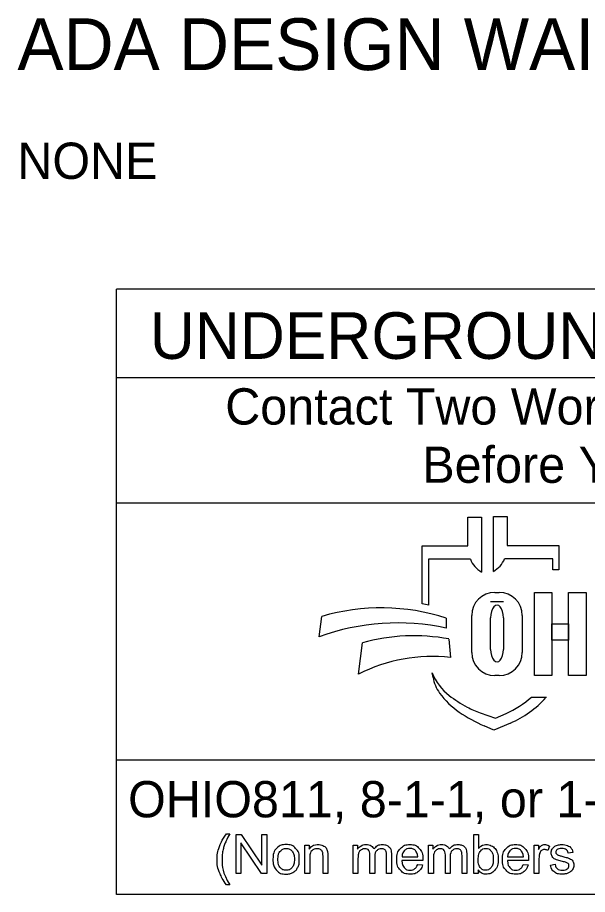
# Model space of a CAD drawing. Extents: x 0 to 34, y 0 to 22.
# Drawn here: x 1.995 to 4.196, y 2.143 to 5.529 of the extents above; entities that cross this region are included whole.
import ezdxf

# ---------------------------------------------------------------- set-up
doc = ezdxf.new("R2010")
doc.units = 0
doc.layers.add('SH_Data', color=7, linetype='Continuous')
doc.layers.add('SH_Text', color=7, linetype='Continuous')

msp = doc.modelspace()

# ---------------------------------------------------------------- linework, layer by layer
at = {"layer": 'SH_Data'}
for p, q in [((2.3775, 2.1428), (2.3775, 4.4803)), ((6.6275, 4.4803), (2.3775, 4.4803)), ((2.3775, 4.1387), (6.6275, 4.1387)), ((2.3775, 3.6553), (6.6275, 3.6553)), ((6.6275, 2.6607), (2.3775, 2.6607)), ((6.6275, 2.1428), (2.3775, 2.1428))]:
    msp.add_line(p, q, dxfattribs=at)
at = {"layer": 'SH_Text'}
for p, q in [((3.7335, 3.4883), (3.7335, 3.5998)), ((3.7335, 3.5998), (3.7872, 3.5998)), ((3.7872, 3.5998), (3.7872, 3.3877)), ((3.8329, 3.39), (3.8329, 3.6021)), ((3.8329, 3.6021), (3.8865, 3.6021)), ((3.8865, 3.6021), (3.8865, 3.4906)), ((3.5576, 3.2644), (3.5576, 3.4883)), ((3.5576, 3.4883), (3.7335, 3.4883)), ((3.8865, 3.4906), (4.0857, 3.4906)), ((4.0857, 3.4906), (4.0857, 3.3968)), ((3.5828, 3.4369), (3.5828, 3.26)), ((3.7439, 3.4369), (3.5828, 3.4369)), ((4.0625, 3.4392), (3.8761, 3.4392)), ((4.0625, 3.3968), (4.0625, 3.4392)), ((4.0857, 3.3968), (4.0625, 3.3968)), ((3.8385, 3.3091), (3.8551, 3.3091)), ((3.8718, 3.2721), (3.822, 3.2721)), ((3.7491, 3.0776), (3.7491, 3.2196)), ((3.9445, 3.2196), (3.9445, 3.0776)), ((3.1602, 3.1381), (3.1696, 3.2162)), ((3.6509, 3.2097), (3.6509, 3.1709)), ((3.822, 3.089), (3.822, 3.2114)), ((3.8718, 3.2114), (3.8718, 3.089)), ((3.6608, 3.1291), (3.6671, 3.0582)), ((3.312, 2.9936), (3.3267, 3.1137)), ((3.5997, 2.9807), (3.5967, 2.9986)), ((3.8551, 2.9882), (3.8385, 2.9882)), ((3.98, 2.9048), (4.0375, 2.9048)), ((3.7816, 2.8444), (3.841, 2.8239)), ((3.841, 2.8239), (3.8821, 2.8417)), ((3.835, 2.7769), (3.7976, 2.7934)), ((3.8983, 2.8044), (3.835, 2.7769))]:
    msp.add_line(p, q, dxfattribs=at)
for points in [[(3.991, 3.3081), (4.0589, 3.3081), (4.0589, 2.9881), (3.991, 2.9881)], [(4.1231, 3.3081), (4.1911, 3.3081), (4.1911, 2.9881), (4.1231, 2.9881)], [(4.0589, 3.1882), (4.1231, 3.1882), (4.1231, 3.1242), (4.0589, 3.1242)]]:
    msp.add_lwpolyline(points, close=True, dxfattribs=at)
for points in [[(2.8021, 2.3766), (2.8153, 2.3766)], [(2.8389, 2.2239), (2.8389, 2.3741), (2.8592, 2.3741), (2.9382, 2.2561), (2.9382, 2.3741), (2.9572, 2.3741), (2.9572, 2.2239), (2.9369, 2.2239), (2.8579, 2.3419), (2.8579, 2.2239), (2.8389, 2.2239)], [(3.7743, 2.2239), (3.7573, 2.2239), (3.7573, 2.3741), (3.7757, 2.3741), (3.7757, 2.3206)], [(3.1048, 2.2239), (3.1048, 2.3328), (3.1214, 2.3328), (3.1214, 2.3173)], [(3.2912, 2.2239), (3.2912, 2.3328), (3.3077, 2.3328), (3.3077, 2.3174)], [(3.5826, 2.2239), (3.5826, 2.3328), (3.5991, 2.3328), (3.5991, 2.3174)], [(3.9904, 2.2239), (3.9904, 2.3328), (4.007, 2.3328), (4.007, 2.3163)], [(4.0495, 2.3293), (4.043, 2.3122)], [(4.1394, 2.3046), (4.1213, 2.3022)], [(3.1233, 2.2833), (3.1233, 2.2239), (3.1048, 2.2239)], [(3.1932, 2.2908), (3.1932, 2.2239), (3.1748, 2.2239), (3.1748, 2.2901)], [(3.3097, 2.2803), (3.3097, 2.2239), (3.2912, 2.2239)], [(3.3743, 2.2871), (3.3743, 2.2239), (3.3559, 2.2239), (3.3559, 2.2946)], [(3.4388, 2.2986), (3.4388, 2.2239), (3.4203, 2.2239), (3.4203, 2.2924)], [(3.56, 2.2736), (3.4788, 2.2736)], [(3.4799, 2.2887), (3.5406, 2.2887)], [(3.601, 2.2803), (3.601, 2.2239), (3.5826, 2.2239)], [(3.6657, 2.2871), (3.6657, 2.2239), (3.6473, 2.2239), (3.6473, 2.2946)], [(3.7301, 2.2986), (3.7301, 2.2239), (3.7117, 2.2239), (3.7117, 2.2924)], [(3.968, 2.2736), (3.8868, 2.2736)], [(3.8879, 2.2887), (3.9486, 2.2887)], [(4.0088, 2.2809), (4.0088, 2.2239), (3.9904, 2.2239)], [(3.5404, 2.2591), (3.5595, 2.2567)], [(3.7743, 2.2375), (3.7743, 2.2239)], [(3.9484, 2.2591), (3.9675, 2.2567)], [(4.053, 2.2564), (4.0712, 2.2593)], [(2.8153, 2.1798), (2.8021, 2.1798)]]:
    msp.add_lwpolyline(points, dxfattribs=at)
for centre, radius, start, end in [((3.8353, 3.4736), 0.0985, 201.9296, 240.7469), ((3.7847, 3.476), 0.0985, 299.2531, 338.0704), ((3.8385, 3.2196), 0.0895, 90, 180), ((3.8551, 3.2196), 0.0895, 0, 90), ((3.4295, 2.4554), 0.8191, 79.2074, 81.0007), ((3.3997, 2.4302), 0.8191, 72.1402, 106.3144), ((3.4628, 2.2991), 0.8919, 77.8238, 109.8274), ((3.5267, 2.4094), 0.7322, 79.44, 105.8467), ((3.5987, 2.4262), 0.6357, 83.8248, 116.8021), ((3.8385, 3.0776), 0.0895, 180, 270), ((3.8551, 3.0776), 0.0895, 270, 0), ((3.7841, 3.0707), 0.2008, 201.0457, 232.5314), ((3.741, 3.0048), 0.1433, 189.6817, 216.0884), ((3.8747, 3.1022), 0.3088, 216.0884, 235.7167), ((3.9766, 3.3219), 0.5173, 232.5314, 241.794), ((3.7387, 3.1722), 0.3602, 293.4582, 312.0712), ((3.7387, 3.1722), 0.401, 293.4582, 317.8286), ((4.0412, 3.3465), 0.6044, 235.7167, 246.2325), ((3.8914, 3.1631), 0.3371, 241.794, 250.9821)]:
    msp.add_arc(centre, radius, start, end, dxfattribs=at)
for centre, start_param, end_param in [((3.8469, 3.2114), 4.712389, 7.853982), ((3.8469, 3.089), 1.570796, 4.712389)]:
    msp.add_ellipse(centre, major_axis=(0, 0.0484), ratio=0.514403, start_param=start_param, end_param=end_param, dxfattribs=at)
for points in [[(2.8021, 2.1798), (2.7869, 2.199), (2.7763, 2.2248), (2.7657, 2.2506), (2.7657, 2.2783), (2.7657, 2.3026), (2.7736, 2.325), (2.7829, 2.3509), (2.8021, 2.3766)], [(2.8153, 2.3766), (2.8029, 2.3553), (2.7989, 2.3462), (2.7927, 2.332), (2.7891, 2.3167), (2.7847, 2.2975), (2.7847, 2.2782), (2.7847, 2.2289), (2.8153, 2.1798)], [(2.9814, 2.2783), (2.9814, 2.3085), (2.9981, 2.3231), (3.0122, 2.3352), (3.0323, 2.3352), (3.0547, 2.3352), (3.069, 2.3205), (3.0832, 2.3058), (3.0832, 2.2799), (3.0832, 2.2589), (3.0769, 2.2469), (3.0706, 2.2348), (3.0586, 2.2282), (3.0466, 2.2215), (3.0323, 2.2215), (3.0095, 2.2215), (2.9954, 2.2362), (2.9814, 2.2508), (2.9814, 2.2783)], [(3.0003, 2.2783), (3.0003, 2.2574), (3.0094, 2.247), (3.0185, 2.2366), (3.0323, 2.2366), (3.046, 2.2366), (3.0551, 2.2471), (3.0642, 2.2575), (3.0642, 2.279), (3.0642, 2.2991), (3.0551, 2.3095), (3.0459, 2.3199), (3.0323, 2.3199), (3.0185, 2.3199), (3.0094, 2.3096), (3.0003, 2.2992), (3.0003, 2.2783)], [(3.1214, 2.3173), (3.1334, 2.3352), (3.156, 2.3352), (3.1659, 2.3352), (3.1741, 2.3316), (3.1823, 2.3281), (3.1864, 2.3224), (3.1905, 2.3166), (3.1922, 2.3087), (3.1932, 2.3036), (3.1932, 2.2908)], [(3.1748, 2.2901), (3.1748, 2.3013), (3.1726, 2.3069), (3.1705, 2.3125), (3.165, 2.3158), (3.1595, 2.3191), (3.1521, 2.3191), (3.1404, 2.3191), (3.1318, 2.3117), (3.1233, 2.3042), (3.1233, 2.2833)], [(3.3077, 2.3174), (3.3128, 2.3254), (3.3214, 2.3303), (3.3299, 2.3352), (3.3407, 2.3352), (3.3528, 2.3352), (3.3606, 2.3301), (3.3683, 2.3251), (3.3715, 2.3161), (3.3844, 2.3352), (3.4051, 2.3352), (3.4213, 2.3352), (3.43, 2.3262), (3.4388, 2.3172), (3.4388, 2.2986)], [(3.3559, 2.2946), (3.3559, 2.3069), (3.3514, 2.313), (3.3469, 2.3191), (3.3366, 2.3191), (3.3288, 2.3191), (3.3222, 2.315), (3.3156, 2.311), (3.3126, 2.3031), (3.3097, 2.2952), (3.3097, 2.2803)], [(3.4203, 2.2924), (3.4203, 2.3035), (3.4185, 2.3083), (3.4168, 2.3132), (3.412, 2.3162), (3.4073, 2.3191), (3.401, 2.3191), (3.3895, 2.3191), (3.3819, 2.3115), (3.3743, 2.3039), (3.3743, 2.2871)], [(3.5595, 2.2567), (3.555, 2.24), (3.5428, 2.2307), (3.5306, 2.2215), (3.5117, 2.2215), (3.4878, 2.2215), (3.4738, 2.2362), (3.4598, 2.2509), (3.4598, 2.2774), (3.4598, 2.3049), (3.474, 2.32), (3.4881, 2.3352), (3.5106, 2.3352), (3.5324, 2.3352), (3.5463, 2.3203), (3.5601, 2.3055), (3.5601, 2.2785), (3.5601, 2.2769), (3.56, 2.2736)], [(3.5406, 2.2887), (3.5394, 2.3025), (3.5337, 2.3094), (3.5249, 2.3201), (3.5108, 2.3201), (3.4981, 2.3201), (3.4894, 2.3115), (3.4808, 2.303), (3.4799, 2.2887)], [(3.5991, 2.3174), (3.6042, 2.3254), (3.6127, 2.3303), (3.6212, 2.3352), (3.6321, 2.3352), (3.6442, 2.3352), (3.6519, 2.3301), (3.6597, 2.3251), (3.6628, 2.3161), (3.6758, 2.3352), (3.6965, 2.3352), (3.7127, 2.3352), (3.7214, 2.3262), (3.7301, 2.3172), (3.7301, 2.2986)], [(3.6473, 2.2946), (3.6473, 2.3069), (3.6428, 2.313), (3.6383, 2.3191), (3.628, 2.3191), (3.6202, 2.3191), (3.6136, 2.315), (3.607, 2.311), (3.604, 2.3031), (3.601, 2.2952), (3.601, 2.2803)], [(3.7117, 2.2924), (3.7117, 2.3035), (3.7099, 2.3083), (3.7081, 2.3132), (3.7034, 2.3162), (3.6987, 2.3191), (3.6923, 2.3191), (3.6809, 2.3191), (3.6733, 2.3115), (3.6657, 2.3039), (3.6657, 2.2871)], [(3.7741, 2.2792), (3.7741, 2.2596), (3.7794, 2.2509), (3.7881, 2.2366), (3.8029, 2.2366), (3.815, 2.2366), (3.8238, 2.2471), (3.8326, 2.2576), (3.8326, 2.2784), (3.8326, 2.2998), (3.8241, 2.3099), (3.8157, 2.3201), (3.8038, 2.3201), (3.7917, 2.3201), (3.7829, 2.3096), (3.7741, 2.299), (3.7741, 2.2792)], [(3.7757, 2.3206), (3.7874, 2.3352), (3.8055, 2.3352), (3.8155, 2.3352), (3.8245, 2.3311), (3.8335, 2.3271), (3.8392, 2.3198), (3.845, 2.3124), (3.8483, 2.3021), (3.8516, 2.2918), (3.8516, 2.28), (3.8516, 2.252), (3.8378, 2.2368), (3.8239, 2.2215), (3.8046, 2.2215), (3.7853, 2.2215), (3.7743, 2.2375)], [(3.9675, 2.2567), (3.963, 2.24), (3.9508, 2.2307), (3.9386, 2.2215), (3.9196, 2.2215), (3.8958, 2.2215), (3.8818, 2.2362), (3.8678, 2.2509), (3.8678, 2.2774), (3.8678, 2.3049), (3.882, 2.32), (3.8961, 2.3352), (3.9186, 2.3352), (3.9404, 2.3352), (3.9543, 2.3203), (3.9681, 2.3055), (3.9681, 2.2785), (3.9681, 2.2769), (3.968, 2.2736)], [(3.9486, 2.2887), (3.9474, 2.3025), (3.9417, 2.3094), (3.9328, 2.3201), (3.9188, 2.3201), (3.9061, 2.3201), (3.8974, 2.3115), (3.8888, 2.303), (3.8879, 2.2887)], [(4.007, 2.3163), (4.0133, 2.3278), (4.0187, 2.3315), (4.0241, 2.3352), (4.0305, 2.3352), (4.0398, 2.3352), (4.0495, 2.3293)], [(4.043, 2.3122), (4.0363, 2.3162), (4.0295, 2.3162), (4.0235, 2.3162), (4.0187, 2.3125), (4.0139, 2.3089), (4.0119, 2.3024), (4.0088, 2.2926), (4.0088, 2.2809)], [(4.1213, 2.3022), (4.1201, 2.3106), (4.1142, 2.3153), (4.1083, 2.3201), (4.0975, 2.3201), (4.0848, 2.3201), (4.0794, 2.3159), (4.0739, 2.3116), (4.0739, 2.306), (4.0739, 2.3024), (4.0762, 2.2995), (4.0785, 2.2966), (4.0833, 2.2946), (4.086, 2.2936), (4.0996, 2.2899), (4.1192, 2.2847), (4.1269, 2.2813), (4.1347, 2.278), (4.1391, 2.2717), (4.1435, 2.2653), (4.1435, 2.2559), (4.1435, 2.2467), (4.1381, 2.2386), (4.1327, 2.2304), (4.1226, 2.226), (4.1124, 2.2215), (4.0996, 2.2215), (4.0784, 2.2215), (4.0672, 2.2303), (4.0561, 2.2391), (4.053, 2.2564)], [(4.0712, 2.2593), (4.0727, 2.2483), (4.0798, 2.2425), (4.0868, 2.2366), (4.0995, 2.2366), (4.1122, 2.2366), (4.1184, 2.2418), (4.1245, 2.247), (4.1245, 2.254), (4.1245, 2.2602), (4.1191, 2.2638), (4.1153, 2.2663), (4.1002, 2.2701), (4.0799, 2.2752), (4.072, 2.2789), (4.0642, 2.2827), (4.0601, 2.2893), (4.0561, 2.2959), (4.0561, 2.3038), (4.0561, 2.3111), (4.0594, 2.3173), (4.0628, 2.3235), (4.0685, 2.3276), (4.0728, 2.3308), (4.0803, 2.333), (4.0877, 2.3352), (4.0962, 2.3352), (4.109, 2.3352), (4.1187, 2.3315), (4.1284, 2.3278), (4.133, 2.3215), (4.1377, 2.3152), (4.1394, 2.3046)], [(3.4788, 2.2736), (3.4799, 2.2557), (3.489, 2.2462), (3.4981, 2.2366), (3.5117, 2.2366), (3.5219, 2.2366), (3.5291, 2.242), (3.5362, 2.2473), (3.5404, 2.2591)], [(3.8868, 2.2736), (3.8879, 2.2557), (3.897, 2.2462), (3.9061, 2.2366), (3.9197, 2.2366), (3.9299, 2.2366), (3.937, 2.242), (3.9442, 2.2473), (3.9484, 2.2591)]]:
    msp.add_open_spline(points, degree=3, dxfattribs=at)

# ---------------------------------------------------------------- texts
for s, height, p in [('ADA DESIGN WAIVERS', 0.2, (1.9944, 5.3256)), ('NONE', 0.14, (1.9944, 4.9056)), ('UNDERGROUND UTILITIES', 0.18, (2.5057, 4.2106)), ('Contact Two Working Days', 0.14, (2.7972, 3.9571)), ('Before You Dig', 0.14, (3.5583, 3.7321)), ('OHIO811, 8-1-1, or 1-800-362-2764', 0.14, (2.422, 2.4406))]:
    msp.add_text(s, height=height, dxfattribs=at).set_placement(p)

doc.saveas('drawing.dxf')
